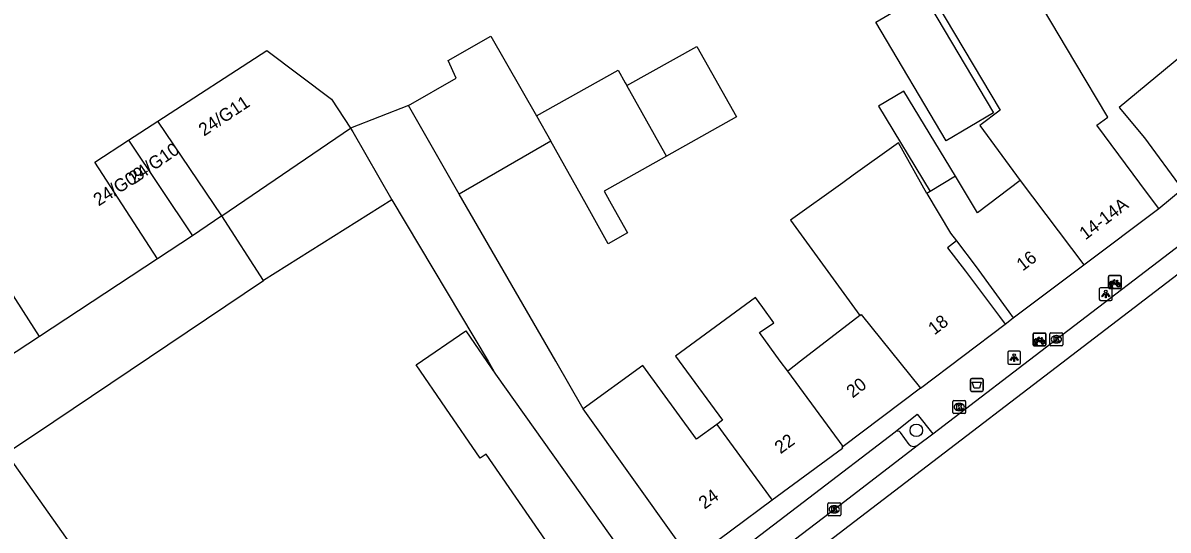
# Model space of a CAD drawing. Extents: x 159377 to 159983, y 382996 to 383595.
# Drawn here: x 159847.9 to 159937, y 383236.9 to 383276.3 of the extents above; entities that cross this region are included whole.
import ezdxf

# ---------------------------------------------------------------- set-up
doc = ezdxf.new("R2010")
doc.units = 0
for name, color, linetype in [('IMGEO_Afvalbak', 7, 'Continuous'), ('IMGEO_Boom', 7, 'Continuous'), ('IMGEO_Fietsenrek', 7, 'Continuous'), ('IMGEO_Kolk', 7, 'Continuous'), ('IMGEO_Lichtpunt', 7, 'Continuous'), ('IMGEO_Pand', 7, 'Continuous'), ('IMGEO_Pand_nummerreeks', 7, 'Continuous'), ('IMGEO_Parkeervlak_open', 7, 'Continuous'), ('IMGEO_Rijbaan_lokaal_gesloten', 7, 'Continuous'), ('IMGEO_Voetpad_open', 7, 'Continuous')]:
    doc.layers.add(name, color=color, linetype=linetype)

msp = doc.modelspace()

# ---------------------------------------------------------------- linework, layer by layer
at = {"layer": 'IMGEO_Afvalbak'}
for p, q in [((159921.6, 383247.75), (159921.6, 383248.55)), ((159921.6, 383248.55), (159921.6, 383247.75)), ((159921.7, 383248.65), (159922.49, 383248.65)), ((159922.49, 383248.65), (159921.7, 383248.65)), ((159922.59, 383248.55), (159922.59, 383247.75)), ((159922.59, 383247.75), (159922.59, 383248.55)), ((159922.49, 383247.65), (159921.7, 383247.65)), ((159921.7, 383247.65), (159922.49, 383247.65))]:
    msp.add_line(p, q, dxfattribs=at)
msp.add_lwpolyline([(159921.743, 383248.364), (159922.447, 383248.364), (159922.298, 383247.894), (159921.892, 383247.894), (159921.743, 383248.364)], dxfattribs=at)
for centre, start, end in [((159921.7, 383248.55), 90, 180), ((159921.7, 383248.55), 90, 180), ((159922.49, 383248.55), 0, 90), ((159922.49, 383248.55), 360, 90), ((159921.7, 383247.75), 180, 270), ((159921.7, 383247.75), 180, 270), ((159922.49, 383247.75), 270, 0), ((159922.49, 383247.75), 270, 0)]:
    msp.add_arc(centre, 0.1, start, end, dxfattribs=at)
at = {"layer": 'IMGEO_Boom'}
msp.add_circle((159917.394, 383244.613), 0.489, dxfattribs=at)
at = {"layer": 'IMGEO_Fietsenrek'}
for p, q in [((159932.345, 383255.729), (159932.345, 383256.57)), ((159932.345, 383256.57), (159932.345, 383255.729)), ((159932.42, 383256.654), (159933.261, 383256.654)), ((159933.261, 383256.654), (159932.42, 383256.654)), ((159933.345, 383256.579), (159933.345, 383255.738)), ((159933.345, 383255.738), (159933.345, 383256.579)), ((159933.27, 383255.654), (159932.429, 383255.654)), ((159932.429, 383255.654), (159933.27, 383255.654)), ((159932.472, 383255.738), (159932.511, 383255.898)), ((159932.506, 383255.738), (159932.472, 383255.738)), ((159932.541, 383255.886), (159932.506, 383255.738)), ((159932.583, 383255.91), (159932.582, 383255.914)), ((159932.624, 383255.738), (159932.59, 383255.88)), ((159932.614, 383255.921), (159932.615, 383255.914)), ((159932.622, 383255.884), (159932.657, 383255.738)), ((159932.657, 383255.738), (159932.624, 383255.738)), ((159933.032, 383256.203), (159933.068, 383256.108)), ((159926.473, 383251.263), (159926.473, 383252.104)), ((159926.473, 383252.104), (159926.473, 383251.263)), ((159926.548, 383252.188), (159927.389, 383252.188)), ((159927.389, 383252.188), (159926.548, 383252.188)), ((159927.473, 383252.113), (159927.473, 383251.272)), ((159927.473, 383251.272), (159927.473, 383252.113)), ((159927.398, 383251.188), (159926.557, 383251.188)), ((159926.557, 383251.188), (159927.398, 383251.188)), ((159926.6, 383251.272), (159926.639, 383251.432)), ((159926.634, 383251.272), (159926.6, 383251.272)), ((159926.669, 383251.42), (159926.634, 383251.272)), ((159926.711, 383251.444), (159926.71, 383251.448)), ((159926.752, 383251.272), (159926.718, 383251.414)), ((159926.742, 383251.455), (159926.743, 383251.448)), ((159926.75, 383251.418), (159926.785, 383251.272)), ((159926.785, 383251.272), (159926.752, 383251.272)), ((159927.16, 383251.737), (159927.196, 383251.642))]:
    msp.add_line(p, q, dxfattribs=at)
for points in [[(159932.658, 383256.18), (159932.753, 383256.344), (159932.839, 383256.33), (159932.841, 383256.321), (159932.785, 383256.31), (159932.758, 383256.265), (159933.014, 383256.224)], [(159932.679, 383256.128), (159932.627, 383256.038), (159932.587, 383256.013), (159932.588, 383256.06), (159932.643, 383256.154)], [(159932.954, 383255.936), (159932.904, 383255.936), (159932.713, 383256.187), (159932.694, 383256.155)], [(159933.001, 383256.199), (159932.744, 383256.24), (159932.727, 383256.211), (159932.894, 383255.991), (159933.001, 383256.199)], [(159933.049, 383256.101), (159933.019, 383256.178), (159932.91, 383255.96), (159932.953, 383255.96)], [(159932.983, 383255.96), (159933.103, 383255.959), (159933.059, 383256.073)], [(159933.079, 383256.08), (159933.134, 383255.935), (159932.984, 383255.935)], [(159933.014, 383256.224), (159933.039, 383256.273), (159933.033, 383256.277), (159933.01, 383256.281), (159932.998, 383256.288), (159932.997, 383256.291), (159932.999, 383256.296), (159933.094, 383256.281), (159933.096, 383256.271), (159933.086, 383256.258), (159933.074, 383256.252), (159933.06, 383256.258), (159933.032, 383256.203)], [(159926.786, 383251.714), (159926.881, 383251.878), (159926.967, 383251.864), (159926.969, 383251.855), (159926.913, 383251.844), (159926.886, 383251.799), (159927.142, 383251.758)], [(159926.807, 383251.662), (159926.755, 383251.572), (159926.715, 383251.547), (159926.716, 383251.594), (159926.771, 383251.688)], [(159927.082, 383251.47), (159927.032, 383251.47), (159926.841, 383251.721), (159926.822, 383251.689)], [(159927.129, 383251.733), (159926.872, 383251.774), (159926.855, 383251.745), (159927.022, 383251.525), (159927.129, 383251.733)], [(159927.177, 383251.635), (159927.147, 383251.712), (159927.038, 383251.494), (159927.081, 383251.494)], [(159927.111, 383251.494), (159927.231, 383251.493), (159927.187, 383251.607)], [(159927.207, 383251.614), (159927.262, 383251.469), (159927.112, 383251.469)], [(159927.142, 383251.758), (159927.167, 383251.807), (159927.161, 383251.811), (159927.138, 383251.815), (159927.126, 383251.822), (159927.125, 383251.825), (159927.127, 383251.83), (159927.222, 383251.815), (159927.224, 383251.805), (159927.214, 383251.792), (159927.202, 383251.786), (159927.188, 383251.792), (159927.16, 383251.737)]]:
    msp.add_lwpolyline(points, dxfattribs=at)
for centre, radius, start, end in [((159932.423, 383256.576), 0.0779, 92.4484, 184.28452), ((159932.423, 383256.576), 0.0779, 92.4484, 184.28452), ((159933.267, 383256.576), 0.0779, 2.4484, 94.28452), ((159933.267, 383256.576), 0.0779, 2.4484, 94.28452), ((159932.423, 383255.732), 0.0779, 182.4484, 274.28452), ((159932.423, 383255.732), 0.0779, 182.4484, 274.28452), ((159932.585, 383256.039), 0.159, 62.67661, 242.13685), ((159932.585, 383256.039), 0.129, 63.31916, 238.90302), ((159932.565, 383255.91), 0.0499, 12.8025, 158.69338), ((159932.585, 383256.039), 0.159, 253.99666, 271.78671), ((159932.565, 383255.91), 0.0174, 12.8025, 163.45023), ((159932.585, 383256.039), 0.129, 253.41502, 269.02044), ((159932.585, 383256.039), 0.129, 283.60429, 43.43025), ((159932.585, 383256.039), 0.159, 283.5766, 46.60424), ((159933.112, 383255.955), 0.159, 113.3408, 178.32165), ((159933.112, 383255.955), 0.159, 187.0065, 105.77075), ((159933.112, 383255.955), 0.129, 113.92302, 177.95563), ((159933.112, 383255.955), 0.129, 188.67146, 104.58832), ((159933.267, 383255.732), 0.0779, 272.4484, 4.28452), ((159933.267, 383255.732), 0.0779, 272.4484, 4.28452), ((159926.551, 383252.11), 0.0779, 92.4484, 184.28452), ((159926.551, 383252.11), 0.0779, 92.4484, 184.28452), ((159927.395, 383252.11), 0.0779, 2.4484, 94.28452), ((159927.395, 383252.11), 0.0779, 2.4484, 94.28452), ((159926.551, 383251.266), 0.0779, 182.4484, 274.28452), ((159926.551, 383251.266), 0.0779, 182.4484, 274.28452), ((159926.713, 383251.573), 0.159, 62.67661, 242.13685), ((159926.713, 383251.573), 0.129, 63.31916, 238.90302), ((159926.693, 383251.444), 0.0499, 12.8025, 158.69338), ((159926.713, 383251.573), 0.159, 253.99666, 271.78671), ((159926.693, 383251.444), 0.0174, 12.8025, 163.45023), ((159926.713, 383251.573), 0.129, 253.41502, 269.02044), ((159926.713, 383251.573), 0.129, 283.60429, 43.43025), ((159926.713, 383251.573), 0.159, 283.5766, 46.60424), ((159927.24, 383251.489), 0.159, 113.3408, 178.32165), ((159927.24, 383251.489), 0.159, 187.0065, 105.77075), ((159927.24, 383251.489), 0.129, 113.92302, 177.95563), ((159927.24, 383251.489), 0.129, 188.67146, 104.58832), ((159927.395, 383251.266), 0.0779, 272.4484, 4.28452), ((159927.395, 383251.266), 0.0779, 272.4484, 4.28452)]:
    msp.add_arc(centre, radius, start, end, dxfattribs=at)
at = {"layer": 'IMGEO_Kolk'}
for p, q in [((159927.79, 383251.279), (159927.79, 383252.131)), ((159927.865, 383252.205), (159928.717, 383252.205)), ((159928.278, 383251.985), (159928.303, 383251.985)), ((159928.791, 383252.131), (159928.791, 383251.279)), ((159928.717, 383251.205), (159927.865, 383251.205)), ((159928.301, 383251.425), (159928.276, 383251.425)), ((159920.227, 383246.003), (159920.227, 383246.855)), ((159920.302, 383246.929), (159921.154, 383246.929)), ((159920.715, 383246.709), (159920.74, 383246.709)), ((159921.228, 383246.855), (159921.228, 383246.003)), ((159921.154, 383245.929), (159920.302, 383245.929)), ((159920.738, 383246.149), (159920.713, 383246.149)), ((159910.502, 383238.043), (159910.502, 383238.895)), ((159910.577, 383238.969), (159911.429, 383238.969)), ((159910.99, 383238.749), (159911.015, 383238.749)), ((159911.503, 383238.895), (159911.503, 383238.043)), ((159911.429, 383237.969), (159910.577, 383237.969)), ((159911.013, 383238.189), (159910.988, 383238.189))]:
    msp.add_line(p, q, dxfattribs=at)
for points in [[(159927.79, 383251.279), (159927.79, 383252.131)], [(159927.865, 383252.205), (159928.717, 383252.205)], [(159928.111, 383251.905), (159928.234, 383251.905), (159928.234, 383251.754), (159928.364, 383251.905), (159928.528, 383251.905), (159928.382, 383251.754), (159928.535, 383251.505), (159928.383, 383251.505), (159928.298, 383251.669), (159928.234, 383251.602), (159928.234, 383251.505), (159928.111, 383251.505), (159928.111, 383251.905)], [(159928.791, 383252.131), (159928.791, 383251.279)], [(159928.717, 383251.205), (159927.865, 383251.205)], [(159920.227, 383246.003), (159920.227, 383246.855)], [(159920.302, 383246.929), (159921.154, 383246.929)], [(159920.548, 383246.629), (159920.671, 383246.629), (159920.671, 383246.478), (159920.801, 383246.629), (159920.965, 383246.629), (159920.819, 383246.478), (159920.972, 383246.229), (159920.82, 383246.229), (159920.735, 383246.393), (159920.671, 383246.326), (159920.671, 383246.229), (159920.548, 383246.229), (159920.548, 383246.629)], [(159921.228, 383246.855), (159921.228, 383246.003)], [(159921.154, 383245.929), (159920.302, 383245.929)], [(159910.502, 383238.043), (159910.502, 383238.895)], [(159910.577, 383238.969), (159911.429, 383238.969)], [(159910.823, 383238.669), (159910.946, 383238.669), (159910.946, 383238.518), (159911.076, 383238.669), (159911.24, 383238.669), (159911.094, 383238.518), (159911.247, 383238.269), (159911.095, 383238.269), (159911.01, 383238.433), (159910.946, 383238.366), (159910.946, 383238.269), (159910.823, 383238.269), (159910.823, 383238.669)], [(159911.503, 383238.895), (159911.503, 383238.043)], [(159911.429, 383237.969), (159910.577, 383237.969)]]:
    msp.add_lwpolyline(points, dxfattribs=at)
for centre, start, end in [((159927.867, 383252.129), 91.55205, 178.44795), ((159927.867, 383252.129), 91.55205, 178.44795), ((159928.715, 383252.129), 1.55205, 88.44795), ((159928.715, 383252.129), 1.55205, 88.44795), ((159927.867, 383251.281), 181.55205, 268.44795), ((159927.867, 383251.281), 181.55205, 268.44795), ((159928.715, 383251.281), 271.55205, 358.44795), ((159928.715, 383251.281), 271.55205, 358.44795), ((159920.304, 383246.853), 91.55205, 178.44795), ((159920.304, 383246.853), 91.55205, 178.44795), ((159921.152, 383246.853), 1.55205, 88.44795), ((159921.152, 383246.853), 1.55205, 88.44795), ((159920.304, 383246.005), 181.55205, 268.44795), ((159920.304, 383246.005), 181.55205, 268.44795), ((159921.152, 383246.005), 271.55205, 358.44795), ((159921.152, 383246.005), 271.55205, 358.44795), ((159910.579, 383238.893), 91.55205, 178.44795), ((159910.579, 383238.893), 91.55205, 178.44795), ((159911.427, 383238.893), 1.55205, 88.44795), ((159911.427, 383238.893), 1.55205, 88.44795), ((159910.579, 383238.045), 181.55205, 268.44795), ((159910.579, 383238.045), 181.55205, 268.44795), ((159911.427, 383238.045), 271.55205, 358.44795), ((159911.427, 383238.045), 271.55205, 358.44795)]:
    msp.add_arc(centre, 0.0765, start, end, dxfattribs=at)
for centre, major_axis, ratio, start_param, end_param in [((159928.277, 383251.705), (-0.387, 0.002), 0.722429, 4.712389, 7.853982), ((159928.302, 383251.705), (-0.39, 0.002), 0.717154, 1.570796, 4.712389), ((159920.714, 383246.429), (-0.387, 0.002), 0.722429, 4.712389, 7.853982), ((159920.739, 383246.429), (-0.39, 0.002), 0.717154, 1.570796, 4.712389), ((159910.989, 383238.469), (-0.387, 0.002), 0.722429, 4.712389, 7.853982), ((159911.014, 383238.469), (-0.39, 0.002), 0.717154, 1.570796, 4.712389)]:
    msp.add_ellipse(centre, major_axis=major_axis, ratio=ratio, start_param=start_param, end_param=end_param, dxfattribs=at)
at = {"layer": 'IMGEO_Lichtpunt'}
for p, q in [((159931.633, 383255.622), (159931.633, 383254.815)), ((159931.633, 383255.622), (159931.633, 383254.815)), ((159932.535, 383255.717), (159931.727, 383255.717)), ((159932.535, 383255.717), (159931.727, 383255.717)), ((159932.629, 383254.815), (159932.629, 383255.622)), ((159932.629, 383254.815), (159932.629, 383255.622)), ((159931.727, 383254.721), (159932.535, 383254.721)), ((159931.727, 383254.721), (159932.535, 383254.721)), ((159924.508, 383250.674), (159924.508, 383249.867)), ((159924.508, 383250.674), (159924.508, 383249.867)), ((159925.41, 383250.769), (159924.602, 383250.769)), ((159925.41, 383250.769), (159924.602, 383250.769)), ((159925.504, 383249.867), (159925.504, 383250.674)), ((159925.504, 383249.867), (159925.504, 383250.674)), ((159924.602, 383249.773), (159925.41, 383249.773)), ((159924.602, 383249.773), (159925.41, 383249.773))]:
    msp.add_line(p, q, dxfattribs=at)
for points in [[(159932.007, 383255.286), (159932.046, 383255.258), (159931.858, 383254.996), (159931.82, 383255.023), (159932.007, 383255.286)], [(159932.109, 383255.238), (159932.156, 383255.238), (159932.156, 383254.916), (159932.109, 383254.916), (159932.109, 383255.238)], [(159932.219, 383255.258), (159932.257, 383255.285), (159932.444, 383255.023), (159932.405, 383254.995), (159932.219, 383255.258)], [(159924.882, 383250.338), (159924.921, 383250.31), (159924.733, 383250.048), (159924.695, 383250.075), (159924.882, 383250.338)], [(159924.984, 383250.29), (159925.031, 383250.29), (159925.031, 383249.968), (159924.984, 383249.968), (159924.984, 383250.29)], [(159925.094, 383250.31), (159925.132, 383250.337), (159925.319, 383250.075), (159925.28, 383250.047), (159925.094, 383250.31)]]:
    msp.add_lwpolyline(points, dxfattribs=at)
for centre in [(159932.132, 383255.42), (159925.007, 383250.472)]:
    msp.add_circle(centre, 0.0994, dxfattribs=at)
for centre, start, end in [((159931.727, 383255.622), 90, 180), ((159931.727, 383255.622), 90, 180), ((159932.535, 383255.622), 0, 90), ((159932.535, 383255.622), 0, 90), ((159931.727, 383254.815), 180, 270), ((159931.727, 383254.815), 180, 270), ((159932.535, 383254.815), 270, 0), ((159932.535, 383254.815), 270, 360), ((159924.602, 383250.674), 90, 180), ((159924.602, 383250.674), 90, 180), ((159925.41, 383250.674), 0, 90), ((159925.41, 383250.674), 0, 90), ((159924.602, 383249.867), 180, 270), ((159924.602, 383249.867), 180, 270), ((159925.41, 383249.867), 270, 0), ((159925.41, 383249.867), 270, 360)]:
    msp.add_arc(centre, 0.0946, start, end, dxfattribs=at)
at = {"layer": 'IMGEO_Pand'}
for points in [[(159936.262, 383261.889), (159935.394, 383263.043), (159931.449, 383268.361), (159932.286, 383268.996), (159929.731, 383273.294), (159916.391, 383295.732), (159913.836, 383300.03), (159907.88, 383296.489)], [(159908.686, 383295.134), (159910.435, 383292.191), (159923.904, 383269.535), (159922.328, 383268.339), (159925.461, 383264.06)], [(159914.231, 383276.374), (159917.912, 383278.563), (159923.401, 383269.331), (159919.72, 383267.142), (159914.231, 383276.374)], [(159877.865, 383269.907), (159881.58, 383272.032), (159880.954, 383273.399), (159884.279, 383275.3), (159887.828, 383269.093)], [(159858.36, 383268.671), (159866.841, 383274.168), (159871.87, 383270.393), (159873.352, 383268.134)], [(159894.863, 383271.443), (159900.315, 383274.499), (159903.396, 383269.004), (159897.944, 383265.948)], [(159938.884, 383274.471), (159933.181, 383269.745), (159935.149, 383267.369), (159938.069, 383263.392)], [(159887.828, 383269.093), (159894.183, 383272.656), (159894.739, 383271.664), (159894.863, 383271.443)], [(159897.944, 383265.948), (159897.612, 383266.54), (159894.863, 383271.443)], [(159920.427, 383264.392), (159916.408, 383271.023), (159914.449, 383269.835), (159918.468, 383263.205)], [(159881.821, 383262.989), (159877.865, 383269.907)], [(159887.828, 383269.093), (159888.942, 383267.107)], [(159856.082, 383267.195), (159858.36, 383268.671)], [(159863.344, 383261.297), (159858.36, 383268.671)], [(159863.344, 383261.297), (159873.352, 383268.134)], [(159873.352, 383268.134), (159873.535, 383267.856), (159876.558, 383262.55)], [(159858.332, 383257.968), (159853.456, 383265.492), (159856.082, 383267.195)], [(159856.082, 383267.195), (159861.058, 383259.76)], [(159888.942, 383267.107), (159881.821, 383262.989)], [(159897.944, 383265.948), (159893.093, 383263.229), (159893.222, 383262.999), (159893.65, 383262.236), (159894.913, 383259.983), (159893.409, 383259.139), (159891.718, 383262.155), (159888.942, 383267.107)], [(159918.196, 383263.04), (159916.013, 383266.999), (159912.475, 383264.462), (159911.671, 383263.885), (159907.607, 383260.971), (159913, 383253.565)], [(159920.427, 383264.392), (159918.468, 383263.205)], [(159925.461, 383264.06), (159922.151, 383261.548), (159920.427, 383264.392)], [(159925.461, 383264.06), (159930.434, 383257.507)], [(159876.558, 383262.55), (159866.58, 383256.276)], [(159918.468, 383263.205), (159918.196, 383263.04)], [(159918.196, 383263.04), (159920.061, 383259.963), (159920.52, 383259.358)], [(159930.434, 383257.507), (159936.262, 383261.889)], [(159863.344, 383261.297), (159861.058, 383259.76)], [(159866.58, 383256.276), (159863.344, 383261.297)], [(159849.15, 383251.931), (159844.202, 383259.616), (159837.09, 383255.036)], [(159861.058, 383259.76), (159858.332, 383257.968)], [(159920.52, 383259.358), (159919.823, 383258.822), (159921.228, 383256.998), (159923.862, 383253.482), (159924.314, 383252.884)], [(159920.52, 383259.358), (159922.053, 383257.339), (159924.582, 383253.827), (159924.928, 383253.367)], [(159858.332, 383257.968), (159849.15, 383251.931)], [(159924.928, 383253.367), (159930.434, 383257.507)], [(159838.941, 383242.708), (159839.084, 383242.514), (159840.201, 383243.3), (159847.444, 383233.016), (159851.5, 383235.872), (159846.589, 383242.843), (159850.254, 383245.306), (159866.58, 383256.276)], [(159907.379, 383249.229), (159906.797, 383250), (159905.181, 383252.229), (159906.311, 383252.986), (159905.444, 383254.169), (159904.87, 383254.952), (159898.643, 383250.386), (159899.218, 383249.602), (159902.302, 383245.397), (159901.857, 383245.074)], [(159913, 383253.565), (159913.087, 383253.632), (159917.716, 383247.898)], [(159913, 383253.565), (159908.37, 383250), (159907.379, 383249.229)], [(159917.716, 383247.898), (159924.314, 383252.884)], [(159849.15, 383251.931), (159840.957, 383246.545)], [(159889.569, 383226.993), (159886.701, 383231.03), (159884.934, 383233.432), (159888.517, 383236.07), (159883.921, 383242.774), (159883.447, 383242.45), (159880.783, 383246.335), (159878.465, 383249.715), (159882.326, 383252.361), (159884.643, 383248.981)], [(159901.857, 383245.074), (159900.273, 383243.925), (159896.094, 383249.664), (159891.454, 383246.285)], [(159911.692, 383243.35), (159907.379, 383249.229)], [(159884.643, 383248.981), (159895.805, 383233.284), (159896.67, 383232.088)], [(159917.716, 383247.898), (159911.692, 383243.35)], [(159899.898, 383234.52), (159898.839, 383235.976), (159891.454, 383246.285)], [(159901.857, 383245.074), (159906.181, 383239.17)], [(159911.692, 383243.35), (159911.587, 383243.271), (159911.635, 383243.207), (159906.181, 383239.17)], [(159906.181, 383239.17), (159899.898, 383234.52)]]:
    msp.add_lwpolyline(points, dxfattribs=at)
at = {"layer": 'IMGEO_Parkeervlak_open'}
msp.add_lwpolyline([(159916.844, 383243.527), (159916.171, 383244.455)], dxfattribs=at)
for centre, radius, start, end in [((159915.932, 383244.2), 0.349, 46.87499, 123.28903), ((159917.19, 383243.821), 0.454, 220.36899, 304.72764)]:
    msp.add_arc(centre, radius, start, end, dxfattribs=at)
at = {"layer": 'IMGEO_Rijbaan_lokaal_gesloten'}
for points in [[(159877.865, 383269.907), (159873.352, 383268.134)], [(159949.02, 383265.371), (159897.491, 383225.958), (159894.22, 383223.535), (159888.449, 383219.325), (159880.097, 383213.321)], [(159876.558, 383262.55), (159884.072, 383250), (159884.643, 383248.981)], [(159891.454, 383246.285), (159889.333, 383250), (159881.821, 383262.989)], [(159918.678, 383244.335), (159928.303, 383251.721), (159938.953, 383259.858), (159939.889, 383260.569), (159942.046, 383262.195)], [(159917.448, 383243.448), (159918.678, 383244.335)], [(159902.531, 383232.027), (159911.142, 383238.598), (159917.448, 383243.448)]]:
    msp.add_lwpolyline(points, dxfattribs=at)
at = {"layer": 'IMGEO_Voetpad_open'}
for points in [[(159936.262, 383261.889), (159938.069, 383263.392)], [(159924.314, 383252.884), (159924.928, 383253.367)], [(159915.741, 383244.492), (159917.468, 383245.881), (159918.678, 383244.335)], [(159901.983, 383233.992), (159909.025, 383239.354), (159915.741, 383244.492)]]:
    msp.add_lwpolyline(points, dxfattribs=at)

# ---------------------------------------------------------------- texts
at = {"layer": 'IMGEO_Pand_nummerreeks'}
for s, rotation, p in [('24/G11', 33.52852, (159861.949, 383267.47)), ('24/G10', 34.77783, (159856.525, 383263.744)), ('24/G09', 32.22888, (159853.739, 383262.032)), ('14-14A', 37.19069, (159930.554, 383259.397)), ('16', 37.19642, (159925.666, 383256.968)), ('18', 37.60322, (159918.794, 383251.991)), ('20', 37.60895, (159912.431, 383247.09)), ('22', 36.06196, (159906.819, 383242.744)), ('24', 36.06196, (159900.907, 383238.439))]:
    msp.add_text(s, height=1, rotation=rotation, dxfattribs=at).set_placement(p)

doc.saveas('drawing.dxf')
